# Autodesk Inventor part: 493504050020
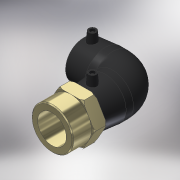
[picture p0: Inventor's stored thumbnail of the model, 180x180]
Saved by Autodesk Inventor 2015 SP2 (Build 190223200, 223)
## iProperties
Created: 2017-06
Part Number: 493504050020
Material: Generic
Description: PLASSON 90° ELBOW FEMALE TRANSITION 50-2''
Document SubType Name: Modeling
Designer: KIM
Mass: 300.376 g
Surface Area: 708.828 cm^2
Volume: 300.376 cm^3
Density: 1 g/cm^3
Appearance: Rubber - Black
Author: KIM
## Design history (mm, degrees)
derived "493504.ipt"
feature "Solid1::493504.ipt"
tag "TaggingFeature1"
body "Solid1"
other parameters: "d2" = 67, "d4" = 36, "d5" = 60.3, "d8" = 168 deg, "d10" = 19.2, "d11" = 6.4, "d29" = 52, "d30" = 15, "d31" = 59.4, "d34" = 5 deg, "d41" = 4, "d42" = 14, "d43" = 0, "d48" = 74.5, "d50" = 42.5, "d51" = 19.2, "d52" = 48, "d54" = 90 deg, "d58" = 48, "d59" = 0, "d61" = 90 deg, "d86" = 3, "d87" = 0, "d93" = 0.1, "d96" = 56.656, "d97" = 38, "d99" = 67, "d100" = 24, "d107" = 12, "d108" = 0, "d109" = 1.5, "d112" = 45 deg, "d113" = 45 deg, "d114" = 2.5, "L_" = 138, "L_1" = 48, "D_" = 38, "A_" = 52, "d_2" = 12, "D_1" = 67, "Rp_" = 56.656
